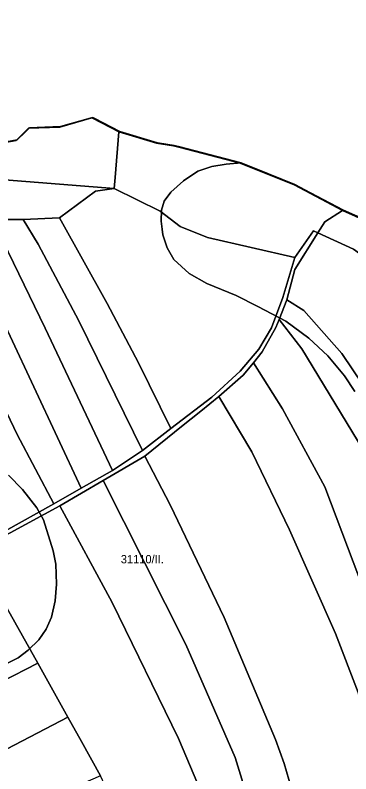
# Model space of a CAD drawing. Extents: x -535894 to -532834, y -1165802 to -1163645.
# Drawn here: x -534690.2 to -534487.4, y -1164561.1 to -1164103.1 of the extents above; entities that cross this region are included whole.
import ezdxf

# ---------------------------------------------------------------- set-up
doc = ezdxf.new("R2010")
doc.units = 0
for name, color, linetype in [('95560013', 7, 'Continuous'), ('95610013', 7, 'Continuous'), ('95620013', 7, 'Continuous'), ('95660013', 7, 'Continuous')]:
    doc.layers.add(name, color=color, linetype=linetype)

msp = doc.modelspace()

# ---------------------------------------------------------------- linework, layer by layer
at = {"layer": '95560013'}
for points in [[(-534783.41, -1164195.59), (-534729.66, -1164199.87), (-534726.97, -1164231.26), (-534720.99, -1164228.44), (-534707.84, -1164266.29), (-534650.37, -1164388.64), (-534666.96, -1164397.98), (-534688.94, -1164356.11), (-534724.82, -1164281.62), (-534728, -1164291.7), (-534735.4, -1164302.05), (-534751.45, -1164315.56), (-534756.49, -1164321.41), (-534793.3, -1164261.64), (-534803.19, -1164251.66), (-534796.15, -1164238.96)], [(-534729.66, -1164199.87), (-534630.4, -1164207.78), (-534641.63, -1164209.34), (-534663.54, -1164225.41), (-534685.41, -1164226.35), (-534704.16, -1164226.38), (-534720.99, -1164228.44), (-534726.97, -1164231.26)], [(-534630.4, -1164207.78), (-534602.67, -1164221.46), (-534590.55, -1164230.7), (-534573.95, -1164237.35), (-534521.14, -1164249.39), (-534528.41, -1164273.53), (-534535.31, -1164291.72), (-534542.92, -1164304.7), (-534554.35, -1164317.99), (-534571.47, -1164333.62), (-534596.12, -1164352.56), (-534615.63, -1164313.03), (-534634.67, -1164277.03), (-534663.54, -1164225.41), (-534641.63, -1164209.34)], [(-534704.16, -1164226.38), (-534672.04, -1164292.08), (-534631.34, -1164377.92), (-534650.37, -1164388.64), (-534707.84, -1164266.29), (-534720.99, -1164228.44)], [(-534685.41, -1164226.35), (-534676.36, -1164241.4), (-534651.82, -1164287.55), (-534613.33, -1164365.78), (-534631.34, -1164377.92), (-534672.04, -1164292.08), (-534704.16, -1164226.38)], [(-534663.54, -1164225.41), (-534634.67, -1164277.03), (-534615.63, -1164313.03), (-534596.12, -1164352.56), (-534613.33, -1164365.78), (-534651.82, -1164287.55), (-534676.36, -1164241.4), (-534685.41, -1164226.35)], [(-534485.85, -1164244.28), (-534469.68, -1164256.06), (-534441.39, -1164280.53), (-534439.7, -1164278.38), (-534420.68, -1164291.71), (-534381.33, -1164307.72), (-534380.51, -1164314.71), (-534392.48, -1164323.34), (-534409.97, -1164335.95), (-534429.42, -1164349.98), (-534454.21, -1164364.71), (-534492.77, -1164307.32), (-534515.72, -1164281.44), (-534526.13, -1164274.97), (-534521.16, -1164256.66), (-534507.27, -1164234.42)], [(-534526.13, -1164274.97), (-534515.72, -1164281.44), (-534492.77, -1164307.32), (-534454.21, -1164364.71), (-534429.42, -1164349.98), (-534416.02, -1164381.41), (-534395.29, -1164442.42), (-534374.06, -1164525.31), (-534335.46, -1164704.47), (-534321.03, -1164764.37), (-534369.38, -1164771.26), (-534395.1, -1164665.47), (-534403.85, -1164623.02), (-534425.95, -1164524.31), (-534441.36, -1164472.55), (-534468.86, -1164391.61), (-534480, -1164365.41), (-534516.93, -1164304.39), (-534530.72, -1164286.68)], [(-534728, -1164291.7), (-534724.82, -1164281.62), (-534688.94, -1164356.11), (-534666.96, -1164397.98), (-534696.51, -1164414.6), (-534717.41, -1164375.63), (-534751.45, -1164315.56), (-534735.4, -1164302.05)], [(-534532.67, -1164291.64), (-534530.72, -1164286.68), (-534516.93, -1164304.39), (-534480, -1164365.41), (-534468.86, -1164391.61), (-534441.36, -1164472.55), (-534425.95, -1164524.31), (-534403.85, -1164623.02), (-534395.1, -1164665.47), (-534369.38, -1164771.26), (-534394.4, -1164775.14), (-534435.14, -1164602.44), (-534447.18, -1164556.51), (-534458.51, -1164505.61), (-534503.01, -1164387.73), (-534528.59, -1164340.68), (-534546.29, -1164312.84), (-534540.94, -1164306.3)], [(-534552.41, -1164320.35), (-534546.29, -1164312.84), (-534528.59, -1164340.68), (-534503.01, -1164387.73), (-534458.51, -1164505.61), (-534447.18, -1164556.51), (-534435.14, -1164602.44), (-534394.4, -1164775.14), (-534417.97, -1164782.81), (-534422.37, -1164761.45), (-534445.23, -1164674.2), (-534452.73, -1164639.92), (-534475.43, -1164538.49), (-534482.99, -1164511.95), (-534496.61, -1164476.36), (-534524.39, -1164413.79), (-534547.27, -1164366.74), (-534567.13, -1164333.28)], [(-534578.03, -1164342.06), (-534567.13, -1164333.28), (-534547.27, -1164366.74), (-534524.39, -1164413.79), (-534496.61, -1164476.36), (-534482.99, -1164511.95), (-534475.43, -1164538.49), (-534452.73, -1164639.92), (-534445.23, -1164674.2), (-534422.37, -1164761.45), (-534417.97, -1164782.81), (-534464.01, -1164796.91), (-534483.14, -1164727.26), (-534507.98, -1164622.35), (-534527.6, -1164554.86), (-534532.98, -1164540.25), (-534563.85, -1164466.68), (-534596.51, -1164398.57), (-534611.82, -1164369.29), (-534589.62, -1164351.4)], [(-534636.96, -1164383.97), (-534611.82, -1164369.29), (-534596.51, -1164398.57), (-534563.85, -1164466.68), (-534532.98, -1164540.25), (-534527.6, -1164554.86), (-534507.98, -1164622.35), (-534483.14, -1164727.26), (-534464.01, -1164796.91), (-534487.57, -1164805.99), (-534533.79, -1164627.84), (-534557.27, -1164551.19), (-534587.12, -1164482.93)], [(-534663.27, -1164399.34), (-534636.96, -1164383.97), (-534587.12, -1164482.93), (-534557.27, -1164551.19), (-534533.79, -1164627.84), (-534487.57, -1164805.99), (-534495.37, -1164808.4), (-534503.46, -1164810.12), (-534512.61, -1164811.26), (-534519.96, -1164775.85), (-534529.51, -1164742.37), (-534548.57, -1164664.74), (-534575.39, -1164577.77), (-534591.62, -1164539.75), (-534631.7, -1164457.63)], [(-534714.26, -1164426.9), (-534663.27, -1164399.34), (-534631.7, -1164457.63), (-534591.62, -1164539.75), (-534575.39, -1164577.77), (-534548.57, -1164664.74), (-534529.51, -1164742.37), (-534519.96, -1164775.85), (-534512.61, -1164811.26), (-534562.14, -1164816.82), (-534585.02, -1164716.41), (-534592.87, -1164689.03), (-534598.52, -1164669.31), (-534600.76, -1164662.66), (-534607.61, -1164642.33), (-534611.82, -1164629.82), (-534620.54, -1164603.95), (-534622.31, -1164599.78), (-534633.48, -1164573.56), (-534638.57, -1164562.2), (-534650.14, -1164541.51), (-534658.33, -1164526.87), (-534676.64, -1164494.15), (-534695.08, -1164461.19)], [(-534695.08, -1164461.19), (-534676.64, -1164494.15), (-534742.58, -1164527.98), (-534745.16, -1164523.82), (-534751.97, -1164512.8), (-534761.39, -1164496.32)], [(-534658.33, -1164526.87), (-534723.13, -1164560.41), (-534734.51, -1164541.31), (-534738.99, -1164533.78), (-534742.58, -1164527.98), (-534676.64, -1164494.15)], [(-534658.33, -1164526.87), (-534650.14, -1164541.51), (-534638.57, -1164562.2), (-534705.03, -1164590.78), (-534723.13, -1164560.41)]]:
    msp.add_lwpolyline(points, close=True, dxfattribs=at)
msp.add_lwpolyline([(-534696.51, -1164414.6), (-534666.96, -1164397.98), (-534650.37, -1164388.64), (-534631.34, -1164377.92), (-534613.33, -1164365.78), (-534596.12, -1164352.56), (-534571.47, -1164333.62), (-534554.35, -1164317.99), (-534542.92, -1164304.7), (-534535.31, -1164291.72), (-534528.41, -1164273.53), (-534521.14, -1164249.39), (-534509.85, -1164233.23), (-534507.27, -1164234.42), (-534521.16, -1164256.66), (-534526.13, -1164274.97), (-534530.72, -1164286.68), (-534532.67, -1164291.64), (-534540.94, -1164306.3), (-534546.29, -1164312.84), (-534552.41, -1164320.35), (-534567.13, -1164333.28), (-534578.03, -1164342.06), (-534589.62, -1164351.4), (-534611.82, -1164369.29), (-534636.96, -1164383.97), (-534663.27, -1164399.34), (-534714.26, -1164426.9)], dxfattribs=at)
at = {"layer": '95610013'}
for points in [[(-534643.92, -1164165.11), (-534627.51, -1164173.48), (-534629.84, -1164201.15), (-534630.4, -1164207.78), (-534729.66, -1164199.87), (-534730.44, -1164190.85), (-534723.07, -1164188.05), (-534719.55, -1164186.71), (-534705.88, -1164181.51), (-534689.58, -1164178.65), (-534682.2, -1164171.34), (-534663.32, -1164170.6)], [(-534604.82, -1164180.29), (-534594.62, -1164181.93), (-534591.23, -1164182.82), (-534554.26, -1164192.45), (-534521.68, -1164205.56), (-534492.39, -1164221.02), (-534503.09, -1164227.73), (-534507.27, -1164234.42), (-534509.85, -1164233.23), (-534521.14, -1164249.39), (-534573.95, -1164237.35), (-534590.55, -1164230.7), (-534602.67, -1164221.46), (-534630.4, -1164207.78), (-534629.84, -1164201.15), (-534627.51, -1164173.48)], [(-534492.39, -1164221.02), (-534477.05, -1164227.75), (-534465.85, -1164242.8), (-534458.72, -1164249.64), (-534446.52, -1164256.91), (-534439.05, -1164259.47), (-534426.3, -1164271.96), (-534424.3, -1164273.92), (-534420.68, -1164291.71), (-534439.7, -1164278.38), (-534441.39, -1164280.53), (-534469.68, -1164256.06), (-534485.85, -1164244.28), (-534507.27, -1164234.42), (-534503.09, -1164227.73)]]:
    msp.add_lwpolyline(points, close=True, dxfattribs=at)
at = {"layer": '95620013'}
msp.add_lwpolyline([(-534735.42, -1163965.07), (-534580.94, -1163997.64), (-534577.82, -1163998.3), (-534429.37, -1164029.61), (-534426.3, -1164271.96), (-534439.05, -1164259.47), (-534446.52, -1164256.91), (-534458.72, -1164249.64), (-534465.85, -1164242.8), (-534477.05, -1164227.75), (-534492.39, -1164221.02), (-534521.68, -1164205.56), (-534554.26, -1164192.45), (-534591.23, -1164182.82), (-534594.62, -1164181.93), (-534604.82, -1164180.29), (-534627.51, -1164173.48), (-534643.92, -1164165.11), (-534663.32, -1164170.6), (-534682.2, -1164171.34), (-534689.58, -1164178.65), (-534705.88, -1164181.51), (-534719.55, -1164186.71)], close=True, dxfattribs=at)
at = {"layer": '95660013'}
for points in [[(-534705.313, -1164181.264), (-534689.018, -1164178.399), (-534684.237, -1164173.666), (-534681.635, -1164171.091), (-534672.23, -1164170.724), (-534662.759, -1164170.354), (-534644.816, -1164165.28), (-534643.356, -1164164.867), (-534642.191, -1164165.461), (-534626.941, -1164173.233), (-534604.257, -1164180.053), (-534594.057, -1164181.691), (-534590.665, -1164182.581), (-534553.695, -1164192.208), (-534562.65, -1164192.974), (-534571.45, -1164194.33), (-534579.867, -1164197.234), (-534588.42, -1164203.01), (-534596.14, -1164209.86), (-534600.201, -1164215.27), (-534601.72, -1164220.85), (-534602.001, -1164227.456), (-534601.393, -1164232.323), (-534600.979, -1164235.643), (-534598.37, -1164243.47), (-534594.3, -1164250.647), (-534585.15, -1164258.92), (-534574.4, -1164264.97), (-534556.669, -1164272.198), (-534543.58, -1164278.99), (-534526.7, -1164287.75), (-534512.831, -1164298.076), (-534501.29, -1164308.689), (-534491.235, -1164320.721), (-534484.96, -1164330.27)], [(-534478.19, -1164226.769), (-534491.819, -1164220.783), (-534511.744, -1164210.267), (-534521.117, -1164205.32), (-534544.673, -1164195.839), (-534553.695, -1164192.208), (-534590.665, -1164182.581), (-534594.057, -1164181.691), (-534604.257, -1164180.053), (-534626.941, -1164173.233), (-534642.191, -1164165.461), (-534643.356, -1164164.867), (-534644.816, -1164165.28), (-534662.759, -1164170.354), (-534672.23, -1164170.724), (-534681.635, -1164171.091), (-534684.237, -1164173.666), (-534689.018, -1164178.399), (-534705.313, -1164181.264)], [(-534484.96, -1164330.27), (-534491.235, -1164320.721), (-534501.29, -1164308.689), (-534512.831, -1164298.076), (-534526.7, -1164287.75), (-534543.58, -1164278.99), (-534556.669, -1164272.198), (-534574.4, -1164264.97), (-534585.15, -1164258.92), (-534594.3, -1164250.647), (-534598.37, -1164243.47), (-534600.979, -1164235.643), (-534601.393, -1164232.323), (-534602.001, -1164227.456), (-534601.72, -1164220.85), (-534600.201, -1164215.27), (-534596.14, -1164209.86), (-534588.42, -1164203.01), (-534579.867, -1164197.234), (-534571.45, -1164194.33), (-534562.65, -1164192.974), (-534553.695, -1164192.208), (-534544.673, -1164195.839), (-534521.117, -1164205.32), (-534511.744, -1164210.267), (-534491.819, -1164220.783), (-534478.19, -1164226.769)], [(-534694.34, -1164380.73), (-534685.81, -1164389.49), (-534677.21, -1164400.48), (-534673.149, -1164407.64), (-534667.181, -1164426.52), (-534665.67, -1164434.48), (-534665.338, -1164446.485), (-534665.98, -1164456.62), (-534668.28, -1164466.511), (-534671.48, -1164473.67), (-534675.94, -1164480.12), (-534682.31, -1164486.49), (-534688.52, -1164491.03), (-534700.23, -1164496.84)], [(-534700.23, -1164496.84), (-534688.52, -1164491.03), (-534682.31, -1164486.49), (-534675.94, -1164480.12), (-534671.48, -1164473.67), (-534668.28, -1164466.511), (-534665.98, -1164456.62), (-534665.338, -1164446.485), (-534665.67, -1164434.48), (-534667.181, -1164426.52), (-534673.149, -1164407.64), (-534677.21, -1164400.48), (-534685.81, -1164389.49), (-534694.34, -1164380.73)]]:
    msp.add_lwpolyline(points, dxfattribs=at)

# ---------------------------------------------------------------- texts
msp.add_text('31110/II.', height=5, rotation=0, dxfattribs=at).set_placement((-534626.391, -1164433.972))

doc.saveas('drawing.dxf')
